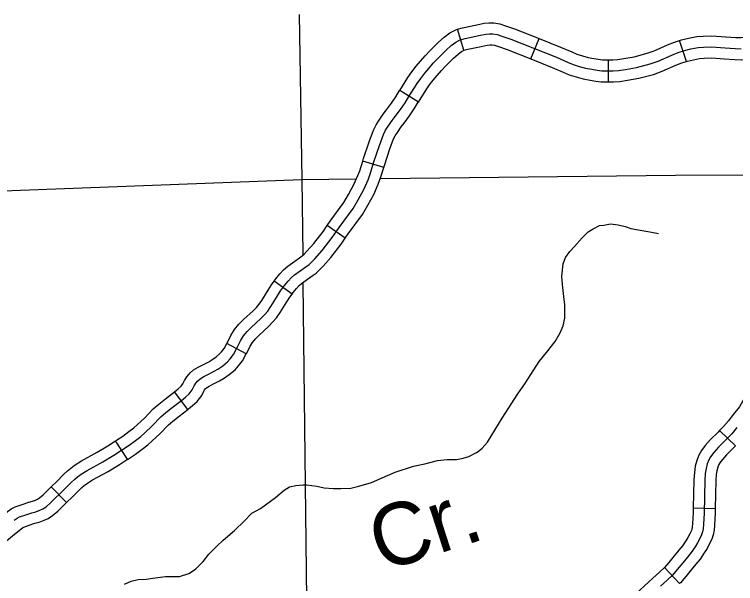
# Model space of a CAD drawing. Extents: x -3711 to 825, y -151 to 1050.
# Drawn here: x -2798.1 to -2743.1, y 468.5 to 512 of the extents above; entities that cross this region are included whole.
import ezdxf

# ---------------------------------------------------------------- set-up
doc = ezdxf.new("R2010")
doc.units = 0
for name, color, linetype in [('Level 32', 7, 'Continuous'), ('Level 35', 7, 'Continuous'), ('Level 5', 7, 'Continuous')]:
    doc.layers.add(name, color=color, linetype=linetype)

msp = doc.modelspace()

# ---------------------------------------------------------------- linework, layer by layer
at = {"layer": 'Level 32'}
for p, q in [((-2763.803, 509.237), (-2764.301, 510.843)), ((-2758.695, 508.575), (-2758.074, 510.138)), ((-2746.829, 508.38), (-2747.342, 509.98)), ((-2752.761, 506.831), (-2752.761, 508.512)), ((-2767.287, 505.272), (-2768.711, 506.167)), ((-2769.931, 500.285), (-2771.538, 500.778)), ((-2772.867, 494.907), (-2774.256, 495.854)), ((-2776.933, 490.633), (-2778.293, 491.622)), ((-2780.43, 486.056), (-2781.912, 486.851)), ((-2784.886, 481.831), (-2785.915, 483.16)), ((-2744.295, 480.207), (-2743.071, 479.055)), ((-2789.479, 478.016), (-2790.398, 479.423)), ((-2794.143, 474.714), (-2795.322, 475.913)), ((-2746.306, 474.319), (-2744.625, 474.273)), ((-2748.496, 469.762), (-2747.349, 468.533))]:
    msp.add_line(p, q, dxfattribs=at)
for points in [[(-2764.301, 510.843), (-2763.923, 510.959), (-2762.827, 511.183), (-2762.272, 511.294), (-2761.9, 511.33), (-2761.537, 511.33), (-2761.079, 511.263), (-2760.638, 511.108), (-2759.941, 510.879), (-2758.074, 510.138)], [(-2772.264, 497.165), (-2771.882, 497.818), (-2771.453, 498.612), (-2771.127, 499.349), (-2770.968, 499.769), (-2770.679, 500.711), (-2770.25, 501.98), (-2769.952, 502.81), (-2769.784, 503.128), (-2769.589, 503.435), (-2769.29, 503.874), (-2769.048, 504.191), (-2768.647, 504.723), (-2768.302, 505.236), (-2768.003, 505.712), (-2767.388, 506.692), (-2767.108, 507.093), (-2766.801, 507.494), (-2766.493, 507.858), (-2766.148, 508.25), (-2765.784, 508.633), (-2765.169, 509.239), (-2764.777, 509.594), (-2764.433, 509.855), (-2764.106, 510.023), (-2763.715, 510.144), (-2762.661, 510.359), (-2762.148, 510.461), (-2761.859, 510.489), (-2761.598, 510.489), (-2761.281, 510.443), (-2760.908, 510.312), (-2760.228, 510.088), (-2756.75, 508.707), (-2755.892, 508.334), (-2755.472, 508.157), (-2755.006, 508.007), (-2754.521, 507.877), (-2754.037, 507.783), (-2753.636, 507.718), (-2753.272, 507.681), (-2752.88, 507.671), (-2752.414, 507.671), (-2752.004, 507.699), (-2751.463, 507.774), (-2750.643, 507.923), (-2749.58, 508.203), (-2748.974, 508.418), (-2747.948, 508.866), (-2747.454, 509.062), (-2746.96, 509.22), (-2746.475, 509.342), (-2745.934, 509.444), (-2745.515, 509.472), (-2744.899, 509.491), (-2743.855, 509.416), (-2743.091, 509.379), (-2742.634, 509.36)], [(-2768.711, 506.167), (-2768.089, 507.156), (-2767.787, 507.589), (-2767.456, 508.022), (-2767.13, 508.407), (-2766.768, 508.817), (-2766.384, 509.222), (-2765.746, 509.85), (-2765.314, 510.241), (-2764.882, 510.569), (-2764.425, 510.804), (-2764.301, 510.843)], [(-2758.074, 510.138), (-2756.427, 509.483), (-2755.561, 509.107), (-2755.18, 508.946), (-2754.769, 508.814), (-2754.332, 508.696), (-2753.89, 508.611), (-2753.525, 508.552), (-2753.219, 508.52), (-2752.87, 508.512), (-2752.761, 508.512)], [(-2752.761, 508.512), (-2752.443, 508.512), (-2752.09, 508.536), (-2751.596, 508.604), (-2750.825, 508.745), (-2749.828, 509.007), (-2749.283, 509.2), (-2748.271, 509.642), (-2747.738, 509.854), (-2747.342, 509.98)], [(-2747.342, 509.98), (-2747.191, 510.029), (-2746.656, 510.163), (-2746.041, 510.28), (-2745.555, 510.312), (-2744.882, 510.332), (-2743.805, 510.255), (-2743.053, 510.219), (-2742.649, 510.202), (-2742.346, 510.226), (-2741.807, 510.281), (-2741.316, 510.321), (-2741.228, 510.323)], [(-2763.803, 509.237), (-2763.506, 509.329), (-2762.495, 509.535), (-2762.025, 509.629), (-2761.819, 509.649), (-2761.66, 509.649), (-2761.483, 509.623), (-2761.178, 509.516), (-2760.514, 509.297), (-2758.695, 508.575)], [(-2767.287, 505.272), (-2766.687, 506.228), (-2766.43, 506.597), (-2766.146, 506.967), (-2765.857, 507.309), (-2765.528, 507.682), (-2765.185, 508.043), (-2764.592, 508.628), (-2764.241, 508.946), (-2763.983, 509.141), (-2763.787, 509.242), (-2763.803, 509.237)], [(-2758.695, 508.575), (-2757.073, 507.931), (-2756.223, 507.561), (-2755.765, 507.368), (-2755.244, 507.201), (-2754.71, 507.057), (-2754.184, 506.956), (-2753.746, 506.884), (-2753.325, 506.841), (-2752.89, 506.831), (-2752.761, 506.831)], [(-2752.761, 506.831), (-2752.386, 506.831), (-2751.918, 506.863), (-2751.331, 506.944), (-2750.46, 507.102), (-2749.332, 507.399), (-2748.665, 507.636), (-2747.625, 508.09), (-2747.17, 508.27), (-2746.829, 508.38)], [(-2746.829, 508.38), (-2746.729, 508.412), (-2746.295, 508.52), (-2745.828, 508.609), (-2745.474, 508.633), (-2744.917, 508.649), (-2743.906, 508.577), (-2743.128, 508.539), (-2742.619, 508.518), (-2742.195, 508.551), (-2741.652, 508.607), (-2741.229, 508.642), (-2741.191, 508.643)], [(-2771.538, 500.778), (-2771.48, 500.969), (-2771.044, 502.257), (-2770.723, 503.151), (-2770.512, 503.55), (-2770.291, 503.897), (-2769.972, 504.366), (-2769.717, 504.699), (-2769.332, 505.211), (-2769.007, 505.694), (-2768.715, 506.159), (-2768.71, 506.167)], [(-2769.931, 500.285), (-2769.879, 500.453), (-2769.457, 501.703), (-2769.181, 502.47), (-2769.057, 502.705), (-2768.886, 502.973), (-2768.608, 503.382), (-2768.378, 503.683), (-2767.962, 504.235), (-2767.597, 504.778), (-2767.292, 505.265), (-2767.287, 505.272)], [(-2774.256, 495.854), (-2774.022, 496.196), (-2772.968, 497.628), (-2772.615, 498.231), (-2772.208, 498.982), (-2771.905, 499.667), (-2771.764, 500.04), (-2771.538, 500.778)], [(-2772.867, 494.907), (-2772.651, 495.223), (-2771.561, 496.702), (-2771.149, 497.406), (-2770.698, 498.241), (-2770.349, 499.03), (-2770.173, 499.497), (-2769.931, 500.285)], [(-2798.138, 473.363), (-2797.923, 473.522), (-2797.727, 473.624), (-2797.261, 473.783), (-2796.795, 473.942), (-2796.497, 474.016), (-2796.18, 474.138), (-2795.947, 474.249), (-2795.704, 474.399), (-2795.369, 474.688), (-2794.296, 475.742), (-2793.802, 476.246), (-2793.522, 476.507), (-2793.299, 476.685), (-2793.019, 476.89), (-2792.581, 477.17), (-2791.378, 477.823), (-2790.539, 478.327), (-2789.868, 478.765), (-2789.364, 479.092), (-2788.879, 479.465), (-2788.478, 479.764), (-2788.171, 480.044), (-2787.602, 480.566), (-2786.94, 481.257), (-2786.567, 481.583), (-2786.073, 481.975), (-2785.374, 482.516), (-2785.075, 482.768), (-2784.786, 483.02), (-2784.544, 483.328), (-2784.404, 483.627), (-2784.283, 483.823), (-2784.124, 484.009), (-2783.947, 484.159), (-2783.677, 484.326), (-2783.257, 484.541), (-2782.875, 484.737), (-2782.604, 484.905), (-2782.222, 485.157), (-2781.868, 485.455), (-2781.663, 485.689), (-2781.411, 486.006), (-2781.141, 486.51), (-2780.87, 487.06), (-2780.628, 487.434), (-2780.357, 487.779), (-2780.05, 488.077), (-2779.313, 488.758), (-2779.033, 489.048), (-2778.782, 489.337), (-2778.539, 489.692), (-2778.045, 490.485), (-2777.803, 490.867), (-2777.504, 491.278), (-2777.225, 491.614), (-2776.992, 491.875), (-2776.74, 492.099), (-2775.873, 492.715), (-2775.621, 492.892), (-2775.416, 493.079), (-2775.183, 493.33), (-2774.623, 493.965), (-2773.859, 494.945), (-2773.337, 495.71), (-2772.264, 497.165)], [(-2778.293, 491.622), (-2778.168, 491.794), (-2777.861, 492.163), (-2777.586, 492.471), (-2777.264, 492.757), (-2776.358, 493.401), (-2776.148, 493.549), (-2776.008, 493.676), (-2775.807, 493.894), (-2775.27, 494.502), (-2774.538, 495.441), (-2774.256, 495.854)], [(-2776.933, 490.633), (-2776.841, 490.761), (-2776.588, 491.065), (-2776.397, 491.279), (-2776.215, 491.44), (-2775.387, 492.028), (-2775.094, 492.235), (-2774.823, 492.481), (-2774.559, 492.767), (-2773.976, 493.428), (-2773.18, 494.449), (-2772.867, 494.907)], [(-2781.912, 486.851), (-2781.888, 486.894), (-2781.603, 487.476), (-2781.312, 487.923), (-2780.984, 488.342), (-2780.628, 488.688), (-2779.901, 489.36), (-2779.653, 489.616), (-2779.448, 489.852), (-2779.243, 490.151), (-2778.757, 490.932), (-2778.498, 491.34), (-2778.293, 491.622)], [(-2780.43, 486.056), (-2780.393, 486.126), (-2780.138, 486.645), (-2779.943, 486.944), (-2779.731, 487.215), (-2779.472, 487.467), (-2778.725, 488.157), (-2778.414, 488.479), (-2778.115, 488.822), (-2777.835, 489.232), (-2777.333, 490.037), (-2777.107, 490.395), (-2776.933, 490.633)], [(-2785.915, 483.16), (-2785.902, 483.17), (-2785.623, 483.406), (-2785.398, 483.602), (-2785.264, 483.772), (-2785.144, 484.027), (-2784.964, 484.319), (-2784.719, 484.607), (-2784.442, 484.84), (-2784.091, 485.059), (-2783.64, 485.289), (-2783.289, 485.469), (-2783.058, 485.613), (-2782.726, 485.832), (-2782.458, 486.058), (-2782.308, 486.228), (-2782.116, 486.47), (-2781.912, 486.851)], [(-2784.886, 481.831), (-2784.845, 481.863), (-2784.528, 482.13), (-2784.174, 482.438), (-2783.823, 482.884), (-2783.663, 483.226), (-2783.601, 483.327), (-2783.529, 483.412), (-2783.452, 483.477), (-2783.263, 483.594), (-2782.874, 483.793), (-2782.461, 484.005), (-2782.151, 484.197), (-2781.718, 484.482), (-2781.278, 484.853), (-2781.017, 485.15), (-2780.706, 485.542), (-2780.43, 486.056)], [(-2741.139, 484.913), (-2741.432, 484.353), (-2741.85, 483.599), (-2742.38, 482.7), (-2742.777, 482.035), (-2743.255, 481.439), (-2743.62, 480.966), (-2743.993, 480.528), (-2744.295, 480.207)], [(-2790.398, 479.423), (-2790.326, 479.47), (-2789.85, 479.779), (-2789.387, 480.135), (-2789.014, 480.413), (-2788.738, 480.664), (-2788.19, 481.167), (-2787.521, 481.865), (-2787.105, 482.229), (-2786.591, 482.637), (-2785.915, 483.16)], [(-2789.479, 478.015), (-2789.409, 478.061), (-2788.878, 478.405), (-2788.372, 478.795), (-2787.943, 479.114), (-2787.603, 479.423), (-2787.014, 479.965), (-2786.359, 480.648), (-2786.029, 480.937), (-2785.554, 481.313), (-2784.886, 481.831)], [(-2742.967, 480.436), (-2743.367, 479.967), (-2743.808, 479.498), (-2744.373, 478.946), (-2744.732, 478.546), (-2744.98, 478.215), (-2745.118, 477.981), (-2745.228, 477.677), (-2745.325, 477.318), (-2745.38, 476.932), (-2745.407, 476.422), (-2745.476, 473.911), (-2745.518, 473.055), (-2745.545, 472.711), (-2745.586, 472.476), (-2745.669, 472.255), (-2745.807, 471.966), (-2745.973, 471.634), (-2746.166, 471.331), (-2746.455, 470.903), (-2746.745, 470.544), (-2747.103, 470.117), (-2747.517, 469.606), (-2747.889, 469.179), (-2748.302, 468.792), (-2748.812, 468.323)], [(-2744.295, 480.207), (-2744.408, 480.087), (-2744.981, 479.528), (-2745.382, 479.08), (-2745.681, 478.682), (-2745.882, 478.34), (-2746.03, 477.93), (-2746.15, 477.488), (-2746.217, 477.014), (-2746.247, 476.456), (-2746.306, 474.319)], [(-2795.322, 475.913), (-2794.891, 476.336), (-2794.389, 476.848), (-2794.071, 477.145), (-2793.809, 477.353), (-2793.494, 477.584), (-2793.008, 477.894), (-2791.795, 478.553), (-2790.985, 479.039), (-2790.398, 479.423)], [(-2743.071, 479.055), (-2743.208, 478.909), (-2743.766, 478.365), (-2744.081, 478.013), (-2744.279, 477.749), (-2744.354, 477.621), (-2744.426, 477.424), (-2744.5, 477.149), (-2744.542, 476.85), (-2744.567, 476.388), (-2744.625, 474.273)], [(-2794.143, 474.714), (-2793.701, 475.148), (-2793.215, 475.644), (-2792.974, 475.87), (-2792.789, 476.016), (-2792.544, 476.196), (-2792.153, 476.445), (-2790.961, 477.093), (-2790.092, 477.614), (-2789.479, 478.016)], [(-2800.149, 472.812), (-2799.935, 472.981), (-2799.172, 473.614), (-2798.65, 474.03), (-2798.371, 474.236), (-2798.06, 474.399), (-2797.532, 474.579), (-2797.033, 474.749), (-2796.75, 474.819), (-2796.512, 474.91), (-2796.35, 474.988), (-2796.202, 475.079), (-2795.938, 475.307), (-2795.322, 475.913)], [(-2799.107, 471.492), (-2798.877, 471.674), (-2798.111, 472.31), (-2797.626, 472.696), (-2797.476, 472.807), (-2797.395, 472.85), (-2796.99, 472.987), (-2796.557, 473.135), (-2796.244, 473.213), (-2795.847, 473.365), (-2795.543, 473.511), (-2795.206, 473.718), (-2794.799, 474.069), (-2794.143, 474.714)], [(-2746.306, 474.319), (-2746.316, 473.943), (-2746.357, 473.109), (-2746.38, 472.817), (-2746.401, 472.698), (-2746.444, 472.584), (-2746.563, 472.334), (-2746.705, 472.049), (-2746.868, 471.792), (-2747.131, 471.404), (-2747.394, 471.078), (-2747.752, 470.651), (-2748.16, 470.147), (-2748.494, 469.763), (-2748.496, 469.762)], [(-2744.625, 474.273), (-2744.636, 473.879), (-2744.679, 473.002), (-2744.71, 472.604), (-2744.772, 472.254), (-2744.895, 471.927), (-2745.051, 471.597), (-2745.24, 471.22), (-2745.463, 470.87), (-2745.779, 470.403), (-2746.095, 470.01), (-2746.454, 469.582), (-2746.873, 469.066), (-2747.283, 468.594), (-2747.349, 468.533)], [(-2748.496, 469.762), (-2748.874, 469.409), (-2749.379, 468.944), (-2750.388, 468.032), (-2751.002, 467.459), (-2751.786, 466.714), (-2752.288, 466.327), (-2752.858, 465.892)]]:
    msp.add_lwpolyline(points, dxfattribs=at)
at = {"layer": 'Level 35'}
for points in [[(-2756.284, 491.356), (-2756.326, 492.008), (-2756.242, 492.932), (-2756.053, 493.415), (-2755.717, 493.878), (-2755.36, 494.256), (-2754.772, 494.928), (-2754.331, 495.369), (-2753.932, 495.601), (-2753.449, 495.853), (-2753.135, 495.895), (-2752.61, 495.979), (-2752.022, 495.916), (-2751.497, 495.79), (-2751.056, 495.643), (-2750.363, 495.495), (-2749.628, 495.369), (-2748.956, 495.243)], [(-2789.731, 468.475), (-2789.206, 468.727), (-2788.681, 468.853), (-2788.072, 468.874), (-2787.547, 468.958), (-2786.602, 469.063), (-2785.51, 469.084), (-2784.818, 469.294), (-2784.293, 469.63), (-2783.705, 470.219), (-2783.285, 470.765), (-2782.676, 471.395), (-2782.193, 471.858), (-2781.332, 472.593), (-2780.576, 473.307), (-2780.01, 473.896), (-2779.338, 474.253), (-2778.204, 475.093), (-2777.532, 475.661), (-2777.133, 475.913), (-2776.629, 476.018), (-2776.083, 476.06), (-2775.789, 476.06), (-2775.033, 475.976), (-2774.488, 475.85), (-2773.795, 475.787), (-2773.207, 475.787), (-2772.451, 475.808), (-2771.821, 475.955), (-2770.876, 476.249), (-2770.057, 476.606), (-2769.05, 477.026), (-2767.664, 477.489), (-2766.803, 477.678), (-2765.816, 477.93), (-2765.081, 477.993), (-2764.388, 477.993), (-2763.864, 478.098), (-2763.423, 478.224), (-2762.856, 478.539), (-2762.73, 478.623), (-2762.415, 478.875), (-2762.016, 479.338), (-2760.882, 481.166), (-2759.706, 483.015), (-2759.16, 483.771), (-2758.468, 484.843), (-2758.069, 485.494), (-2757.502, 486.166), (-2756.851, 487.007), (-2756.452, 487.679), (-2756.221, 488.205), (-2756.116, 488.793), (-2756.116, 489.822), (-2756.158, 490.222), (-2756.284, 491.356)]]:
    msp.add_lwpolyline(points, dxfattribs=at)
at = {"layer": 'Level 5'}
for points in [[(-2776.381, 511.974), (-2776.186, 499.374), (-2776.119, 493.64)], [(-2825.867, 497.481), (-2776.186, 499.374), (-2772.065, 499.423)], [(-2770.15, 499.445), (-2747.645, 499.711), (-2731.692, 499.787)], [(-2776.094, 491.448), (-2775.738, 460.716)]]:
    msp.add_lwpolyline(points, dxfattribs=at)

# ---------------------------------------------------------------- texts
at = {"layer": 'Level 35'}
msp.add_text('Cr.', height=4.7343, rotation=17.8934, dxfattribs=at).set_placement((-2770.103, 469.391))

doc.saveas('drawing.dxf')
